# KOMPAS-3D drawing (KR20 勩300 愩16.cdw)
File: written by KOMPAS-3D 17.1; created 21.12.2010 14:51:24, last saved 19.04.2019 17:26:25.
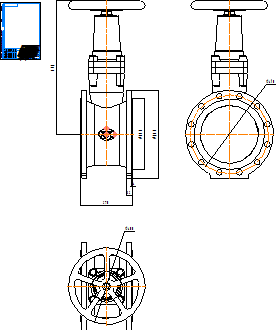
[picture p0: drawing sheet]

Title block, sheet 1: name: KR20 Ду300 Ру16; material: Внимание! Данный продукт является объектом авторского права ООО «Торговый Дом АДЛ». / Запрещается изменение, копирование, распространение / (в том числе путем копирования на другие сайты и ресурсы в Интернете) / или любое иное использование информации и объектов без предварительного / согласия правообладателя (ООО «Торговый Дом АДЛ»).; scale: 1:1; sheets: 1; organisation: ООО "Торговый дом АДЛ"; sheet format: A4; stored path: \\adlc.lan\data\АДЛ_ПКД\3D-модели\ADL production\Клиновые задвижки серии KR ГРАНАР\Клиновые задвижки KR20\KOMPAS 2D\KR20 Ду300 Ру16.cdw

Views: Спереди 1, Проекционный вид 2, Проекционный вид 3
Dimensions and other numbers on the sheet: 4; 32; 270; 370; 460; 694; 410; 400; 1:1; 1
